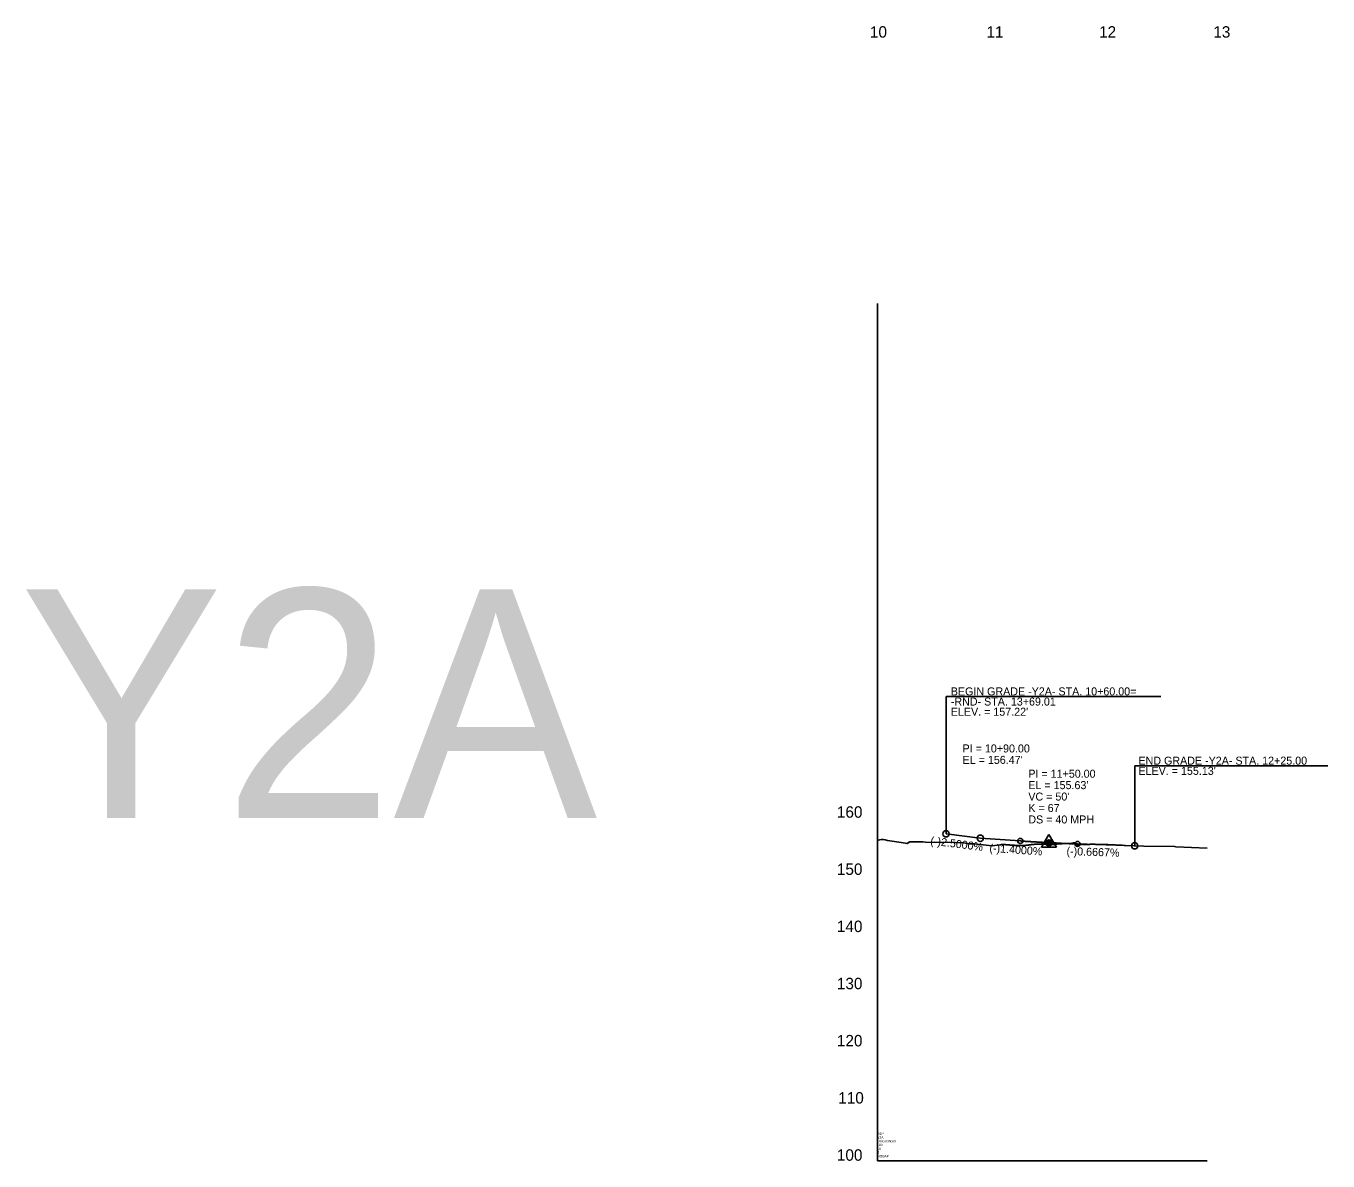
# Model space of a CAD drawing. Extents: x 1778432 to 1784301, y 601022 to 621789.
# Drawn here: x 1779398 to 1780537, y 616039 to 617032 of the extents above; entities that cross this region are included whole.
import ezdxf

# ---------------------------------------------------------------- set-up
doc = ezdxf.new("R2010")
doc.units = 0
for name, color, linetype in [('Exist Profile Cell', 7, 'Continuous'), ('Exist Vertical Profile Ground Line', 7, 'Continuous'), ('Exist Vertical Profile Horizontal Axis Label Major', 7, 'Continuous'), ('Exist Vertical Profile Vertical Axis Label', 7, 'Continuous'), ('Prop PFL Text', 7, 'Continuous'), ('Prop PFL VPI Symbol CELL', 7, 'Continuous'), ('Prop Vertical Profile Curve Label', 7, 'Continuous'), ('Prop Vertical Profile Grade', 7, 'Continuous'), ('Prop Vertical Profile Grade Label', 7, 'Continuous'), ('Prop VPI Label', 7, 'Continuous')]:
    doc.layers.add(name, color=color, linetype=linetype)

msp = doc.modelspace()

# ---------------------------------------------------------------- linework, layer by layer
at = {"layer": 'Exist Profile Cell'}
for q in [(1780143, 616789.2), (1780431.3, 616039.2), (1780143, 616039.2)]:
    msp.add_line((1780143, 616039.2), q, dxfattribs=at)
at = {"layer": 'Exist Vertical Profile Ground Line'}
for points in [[(1780143, 616319.5), (1780143.8, 616319.7), (1780144.9, 616320), (1780146.3, 616320.5), (1780146.9, 616320.5), (1780148, 616320.4), (1780149.7, 616320), (1780151.7, 616319.5), (1780156, 616318.8), (1780167.5, 616317.1), (1780168.8, 616316.9), (1780171.5, 616318.4), (1780182, 616318.3), (1780182.6, 616318.3), (1780185.1, 616318), (1780199.4, 616317.8), (1780201.1, 616317.8), (1780204.6, 616318), (1780210.9, 616317.8), (1780218.7, 616317.3), (1780223.4, 616316.7), (1780227.4, 616316.5), (1780238, 616315.4), (1780243.3, 616314.8), (1780250.1, 616315.7), (1780250.8, 616315.8), (1780251.5, 616315.9), (1780252.2, 616316), (1780253.1, 616316.1), (1780253.6, 616316), (1780254.3, 616316), (1780255, 616315.9), (1780255.7, 616315.8), (1780256.4, 616315.8), (1780257.1, 616315.7), (1780257.8, 616315.6), (1780258.5, 616315.6), (1780259.2, 616315.5), (1780259.8, 616315.4), (1780260.5, 616315.4), (1780261.4, 616315.3), (1780261.9, 616315.3), (1780262.6, 616315.3), (1780263.3, 616315.2), (1780264, 616315.2), (1780264.7, 616315.2), (1780265.4, 616315.2), (1780266.1, 616315.1), (1780266.8, 616315.1), (1780267.5, 616315.1), (1780268.2, 616315.1), (1780268.8, 616315.1), (1780269.5, 616315), (1780270.4, 616315), (1780270.9, 616315.1), (1780271.6, 616315.1), (1780272.3, 616315.2), (1780273, 616315.3), (1780273.7, 616315.4), (1780274.4, 616315.5), (1780275.1, 616315.5), (1780275.8, 616315.6), (1780276.5, 616315.7), (1780277.2, 616315.8), (1780277.9, 616315.9), (1780278.5, 616316), (1780279.2, 616316.1), (1780279.9, 616316.1), (1780280.6, 616316.2), (1780281.3, 616316.3), (1780282, 616316.4), (1780282.7, 616316.4), (1780283.4, 616316.4), (1780284.1, 616316.4), (1780284.8, 616316.4), (1780285.5, 616316.4), (1780286.2, 616316.4), (1780286.9, 616316.5), (1780287.5, 616316.5), (1780288.2, 616316.5), (1780288.9, 616316.4), (1780289.6, 616316.4), (1780290.3, 616316.4), (1780291, 616316.3), (1780291.7, 616316.3), (1780292.4, 616316.2), (1780293.1, 616316.2), (1780293.8, 616316.2), (1780294.5, 616316.1), (1780295.2, 616316.1), (1780295.9, 616316.1), (1780296.6, 616316), (1780297.2, 616316.1), (1780297.9, 616316.2), (1780298.6, 616316.3), (1780299.3, 616316.3), (1780300, 616316.4), (1780300.7, 616316.5), (1780301.4, 616316.6), (1780302.1, 616316.6), (1780302.5, 616316.7), (1780302.8, 616316.7), (1780303.5, 616316.7), (1780304.2, 616316.7), (1780304.9, 616316.8), (1780305.6, 616316.8), (1780306.3, 616316.8), (1780306.9, 616316.8), (1780307.6, 616316.8), (1780308.3, 616316.9), (1780309, 616316.9), (1780309.7, 616316.9), (1780310.4, 616316.9), (1780311.1, 616316.9), (1780311.9, 616317), (1780312.5, 616317), (1780313.2, 616317.1), (1780313.9, 616317.2), (1780314.6, 616317.3), (1780315.4, 616317.4), (1780315.9, 616317.3), (1780316.4, 616317.3), (1780317, 616314.9), (1780317.7, 616315.2), (1780318, 616315.3), (1780318.7, 616315.5), (1780319.1, 616315.7), (1780319.4, 616315.7), (1780320.1, 616315.8), (1780320.8, 616315.9), (1780321.5, 616316.1), (1780321.8, 616316.2), (1780322.2, 616316.2), (1780322.8, 616316.1), (1780323.6, 616316.1), (1780324.3, 616316.1), (1780324.9, 616316.1), (1780325.6, 616316.1), (1780326.3, 616316.1), (1780327, 616316.1), (1780327.7, 616316.1), (1780328.4, 616316.1), (1780329.1, 616316.2), (1780329.8, 616316.2), (1780330.7, 616316.2), (1780331.2, 616316.2), (1780331.9, 616316.2), (1780332.6, 616316.2), (1780333.3, 616316.2), (1780334, 616316.1), (1780334.3, 616316.1), (1780334.6, 616316.1), (1780335.3, 616316.1), (1780336, 616316.1), (1780336.7, 616316.1), (1780337.4, 616316.1), (1780338.1, 616316.1), (1780338.8, 616316.1), (1780339.5, 616316.1), (1780340.3, 616316), (1780340.9, 616316), (1780341.6, 616316), (1780342.5, 616316), (1780344.4, 616315.9), (1780350.4, 616315.8), (1780350.8, 616315.7), (1780357, 616315.3), (1780358.9, 616315.1), (1780376, 616314.6), (1780402.7, 616314.1), (1780404.1, 616314), (1780431.3, 616312.9)], [(1780143, 616319.5), (1780143.8, 616319.7), (1780144.9, 616320), (1780146.3, 616320.5), (1780146.9, 616320.5), (1780148, 616320.4), (1780149.7, 616320), (1780151.7, 616319.5), (1780156, 616318.8), (1780167.7, 616317.1), (1780169.1, 616316.9), (1780171.5, 616318.4), (1780182, 616318.3), (1780182.6, 616318.3), (1780185.1, 616318), (1780199.4, 616317.8), (1780201.1, 616317.8), (1780204.6, 616318), (1780210.9, 616317.8), (1780218.7, 616317.3), (1780223.4, 616316.7), (1780227.4, 616316.5), (1780238, 616315.4), (1780243.3, 616314.8), (1780250.1, 616315.7), (1780250.8, 616315.8), (1780251.5, 616315.9), (1780252.2, 616316), (1780253.1, 616316.1), (1780253.6, 616316), (1780254.3, 616316), (1780255, 616315.9), (1780255.7, 616315.8), (1780256.4, 616315.8), (1780257.1, 616315.7), (1780257.8, 616315.6), (1780258.5, 616315.6), (1780259.2, 616315.5), (1780259.8, 616315.4), (1780260.5, 616315.4), (1780261.4, 616315.3), (1780261.9, 616315.3), (1780262.6, 616315.3), (1780263.3, 616315.2), (1780264, 616315.2), (1780264.7, 616315.2), (1780265.4, 616315.2), (1780266.1, 616315.1), (1780266.8, 616315.1), (1780267.5, 616315.1), (1780268.2, 616315.1), (1780268.8, 616315.1), (1780269.5, 616315), (1780270.4, 616315), (1780270.9, 616315.1), (1780271.6, 616315.1), (1780272.3, 616315.2), (1780273, 616315.3), (1780273.7, 616315.4), (1780274.4, 616315.5), (1780275.1, 616315.5), (1780275.8, 616315.6), (1780276.5, 616315.7), (1780277.2, 616315.8), (1780277.9, 616315.9), (1780278.5, 616316), (1780279.2, 616316.1), (1780279.9, 616316.1), (1780280.6, 616316.2), (1780281.3, 616316.3), (1780282, 616316.4), (1780282.7, 616316.4), (1780283.4, 616316.4), (1780284.1, 616316.4), (1780284.8, 616316.4), (1780285.5, 616316.4), (1780286.2, 616316.4), (1780286.9, 616316.5), (1780287.5, 616316.5), (1780288.2, 616316.5), (1780288.9, 616316.4), (1780289.6, 616316.4), (1780290.3, 616316.4), (1780291, 616316.3), (1780291.7, 616316.3), (1780292.4, 616316.2), (1780293.1, 616316.2), (1780293.8, 616316.2), (1780294.5, 616316.1), (1780295.2, 616316.1), (1780295.9, 616316.1), (1780296.6, 616316), (1780297.2, 616316.1), (1780297.9, 616316.2), (1780298.6, 616316.3), (1780299.3, 616316.3), (1780300, 616316.4), (1780300.7, 616316.5), (1780301.4, 616316.6), (1780302.1, 616316.6), (1780302.5, 616316.7)]]:
    msp.add_lwpolyline(points, dxfattribs=at)
at = {"layer": 'Prop PFL VPI Symbol CELL'}
for p, q in [((1780293, 616324.8), (1780286.5, 616313.6)), ((1780293, 616324.8), (1780299.5, 616313.6)), ((1780286.5, 616313.6), (1780299.5, 616313.6))]:
    msp.add_line(p, q, dxfattribs=at)
for radius in [1.75, 1.2]:
    msp.add_circle((1780293, 616317.3), radius, dxfattribs=at)
at = {"layer": 'Prop Vertical Profile Curve Label'}
for centre in [(1780268, 616319.1), (1780318, 616316.5)]:
    msp.add_circle(centre, 2.25, dxfattribs=at)
at = {"layer": 'Prop Vertical Profile Grade'}
for p, q in [((1780203, 616325.3), (1780233, 616321.5)), ((1780233, 616321.5), (1780268, 616319.1)), ((1780318, 616316.5), (1780368, 616314.8))]:
    msp.add_line(p, q, dxfattribs=at)
msp.add_spline([(1780268, 616319.1), (1780269, 616319), (1780270, 616318.9), (1780271, 616318.9), (1780272, 616318.8), (1780273, 616318.7), (1780274, 616318.7), (1780275, 616318.6), (1780276, 616318.5), (1780277, 616318.5), (1780278, 616318.4), (1780279, 616318.4), (1780280, 616318.3), (1780281, 616318.2), (1780282, 616318.2), (1780283, 616318.1), (1780284, 616318.1), (1780285, 616318), (1780286, 616317.9), (1780287, 616317.9), (1780288, 616317.8), (1780289, 616317.8), (1780290, 616317.7), (1780291, 616317.7), (1780292, 616317.6), (1780293, 616317.6), (1780294, 616317.5), (1780295, 616317.5), (1780296, 616317.4), (1780297, 616317.4), (1780298, 616317.3), (1780299, 616317.3), (1780300, 616317.2), (1780301, 616317.2), (1780302, 616317.1), (1780303, 616317.1), (1780304, 616317), (1780305, 616317), (1780306, 616316.9), (1780307, 616316.9), (1780308, 616316.9), (1780309, 616316.8), (1780310, 616316.8), (1780311, 616316.7), (1780312, 616316.7), (1780313, 616316.7), (1780314, 616316.6), (1780315, 616316.6), (1780316, 616316.6), (1780317, 616316.5), (1780318, 616316.5)], degree=3, dxfattribs=at)
at = {"layer": 'Prop VPI Label'}
for p, q in [((1780203, 616325.3), (1780203, 616445.3)), ((1780203, 616445.3), (1780390.9, 616445.3)), ((1780368, 616314.8), (1780368, 616384.8)), ((1780368, 616384.8), (1780537, 616384.8)), ((1780268, 616319.1), (1780290.2, 616317.5)), ((1780318, 616316.5), (1780295.7, 616317.2))]:
    msp.add_line(p, q, dxfattribs=at)
for centre in [(1780203, 616325.3), (1780233, 616321.5), (1780293, 616317.3), (1780368, 616314.8)]:
    msp.add_circle(centre, 2.75, dxfattribs=at)

# ---------------------------------------------------------------- texts
at = {"layer": 'Exist Profile Cell'}
for s, p in [('Y2A', (1780143, 616058.7)), ('RDY', (1780143, 616061.9)), ('1000.000000', (1780143, 616055.4)), ('100', (1780143, 616052.2)), ('10', (1780143, 616048.9)), ('2', (1780143, 616045.7)), ('NOGAP', (1780143, 616042.4))]:
    msp.add_text(s, height=2, dxfattribs=at).set_placement(p)
at = {"layer": 'Exist Vertical Profile Horizontal Axis Label Major'}
for s, p in [('10', (1780136.5, 617021.7)), ('11', (1780238.4, 617021.7)), ('12', (1780336.9, 617021.7)), ('13', (1780436.8, 617021.7))]:
    msp.add_text(s, height=10, dxfattribs=at).set_placement(p)
at = {"layer": 'Exist Vertical Profile Vertical Axis Label'}
for s, p in [('160', (1780107.6, 616339.4)), ('150', (1780107.6, 616289.4)), ('140', (1780107.6, 616239.4)), ('130', (1780107.6, 616189.4)), ('120', (1780107.6, 616139.4)), ('110', (1780108.8, 616089.4)), ('100', (1780107.6, 616039.4))]:
    msp.add_text(s, height=10, dxfattribs=at).set_placement(p)
at = {"layer": 'Prop PFL Text'}
msp.add_text('Y2A', height=200, dxfattribs=at).set_placement((1779392.6, 616339.2))
at = {"layer": 'Prop Vertical Profile Curve Label'}
for s, p in [("VC = 50'", (1780275, 616354.4)), ('K = 67', (1780275, 616344.4)), ('DS = 40 MPH', (1780275, 616334.4))]:
    msp.add_text(s, height=7, dxfattribs=at).set_placement(p)
at = {"layer": 'Prop Vertical Profile Grade Label'}
for s, rotation, p in [('(-)2.5000%', 352.875, (1780189, 616316)), ('(-)1.4000%', 355.9767, (1780240.8, 616309.6)), ('(-)0.6667%', 358.1073, (1780308.3, 616306.8))]:
    msp.add_text(s, height=7, rotation=rotation, dxfattribs=at).set_placement(p)
at = {"layer": 'Prop VPI Label'}
for s, p in [('BEGIN GRADE -Y2A- STA. 10+60.00=', (1780207.2, 616446.4)), ('-RND- STA. 13+69.01', (1780207.2, 616437.5)), ("ELEV. = 157.22'", (1780207.2, 616428.6)), ('PI = 10+90.00', (1780217.5, 616396.5)), ("EL = 156.47'", (1780217.5, 616386.5)), ('END GRADE -Y2A- STA. 12+25.00', (1780371.3, 616385.8)), ('PI = 11+50.00', (1780275, 616374.4)), ("ELEV. = 155.13'", (1780371.3, 616376.9)), ("EL = 155.63'", (1780275, 616364.4))]:
    msp.add_text(s, height=7, dxfattribs=at).set_placement(p)

doc.saveas('drawing.dxf')
